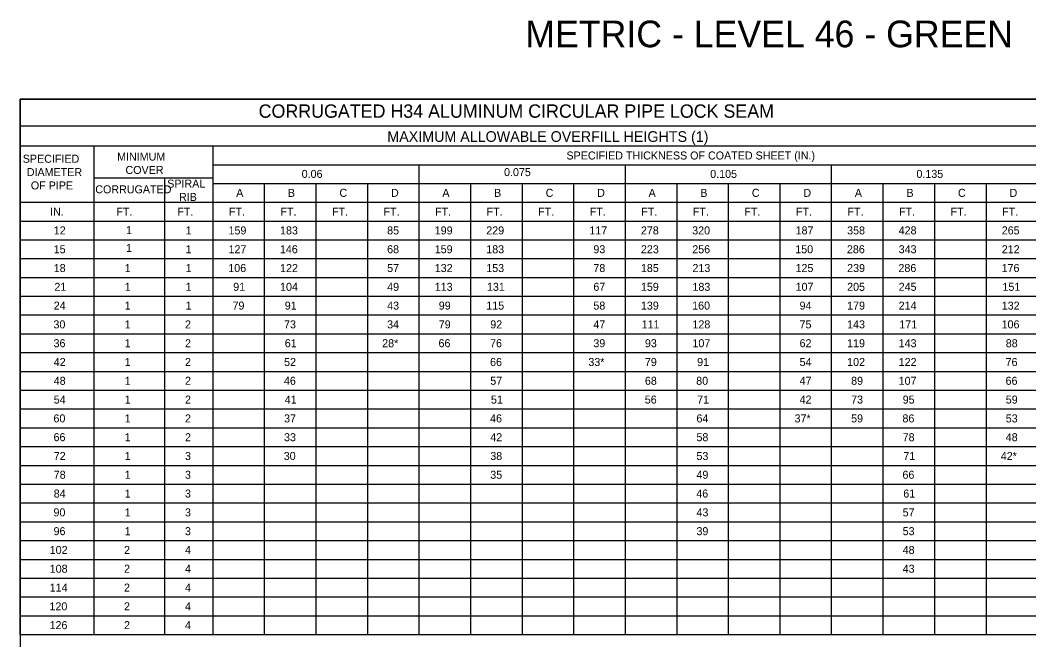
# Model space of a CAD drawing. Extents: x -439.1 to -407.9, y -458.1 to -436.2.
# Drawn here: x -439.11 to -420.2, y -447.81 to -436.2 of the extents above; entities that cross this region are included whole.
import ezdxf

# ---------------------------------------------------------------- set-up
doc = ezdxf.new("R2010")
doc.units = 0
for name, color, linetype in [('Draft_Named_Boundary', 7, 'Continuous'), ('Level 4', 7, 'Continuous'), ('Level 46', 7, 'Continuous')]:
    doc.layers.add(name, color=color, linetype=linetype)

msp = doc.modelspace()

# ---------------------------------------------------------------- linework, layer by layer
at = {"layer": 'Draft_Named_Boundary'}
msp.add_lwpolyline([(-439.109, -458.051), (-407.859, -458.051), (-407.859, -437.676), (-439.109, -437.676)], close=True, dxfattribs=at)
at = {"layer": 'Level 4'}
for p, q in [((-439.109, -437.676), (-416.17, -437.676)), ((-439.109, -447.71), (-439.109, -437.676)), ((-439.109, -438.177), (-416.17, -438.177)), ((-439.109, -438.552), (-416.17, -438.552)), ((-437.72, -447.71), (-437.72, -438.552)), ((-435.493, -447.71), (-435.493, -438.552)), ((-435.493, -438.905), (-416.17, -438.905)), ((-431.629, -447.71), (-431.629, -438.905)), ((-427.764, -447.71), (-427.764, -438.905)), ((-423.9, -447.71), (-423.9, -438.905)), ((-437.72, -439.154), (-435.493, -439.154)), ((-436.396, -447.71), (-436.396, -439.154)), ((-435.493, -439.257), (-416.17, -439.257)), ((-434.527, -447.71), (-434.527, -439.257)), ((-433.561, -447.71), (-433.561, -439.257)), ((-432.595, -447.71), (-432.595, -439.257)), ((-430.663, -447.71), (-430.663, -439.257)), ((-429.696, -447.71), (-429.696, -439.257)), ((-428.73, -447.71), (-428.73, -439.257)), ((-426.798, -447.71), (-426.798, -439.257)), ((-425.832, -447.71), (-425.832, -439.257)), ((-424.866, -447.71), (-424.866, -439.257)), ((-422.933, -447.71), (-422.933, -439.257)), ((-421.967, -447.71), (-421.967, -439.257)), ((-421.001, -447.71), (-421.001, -439.257)), ((-439.109, -439.609), (-416.17, -439.609)), ((-439.109, -439.961), (-416.17, -439.961)), ((-439.109, -440.313), (-416.17, -440.313)), ((-439.109, -440.666), (-416.17, -440.666)), ((-439.109, -441.018), (-416.17, -441.018)), ((-439.109, -441.37), (-416.17, -441.37)), ((-439.109, -441.722), (-416.17, -441.722)), ((-439.109, -442.075), (-416.17, -442.075)), ((-439.109, -442.427), (-416.17, -442.427)), ((-439.109, -442.779), (-416.17, -442.779)), ((-439.109, -443.131), (-416.17, -443.131)), ((-439.109, -443.483), (-416.17, -443.483)), ((-439.109, -443.836), (-416.17, -443.836)), ((-439.109, -444.188), (-416.17, -444.188)), ((-439.109, -444.54), (-416.17, -444.54)), ((-439.109, -444.892), (-416.17, -444.892)), ((-439.109, -445.245), (-416.17, -445.245)), ((-439.109, -445.597), (-416.17, -445.597)), ((-439.109, -445.949), (-416.17, -445.949)), ((-439.109, -446.301), (-416.17, -446.301)), ((-439.109, -446.654), (-416.17, -446.654)), ((-439.109, -447.006), (-416.17, -447.006)), ((-439.109, -447.358), (-416.17, -447.358)), ((-439.109, -447.71), (-416.17, -447.71))]:
    msp.add_line(p, q, dxfattribs=at)

# ---------------------------------------------------------------- texts
for s, height, p in [('CORRUGATED H34 ALUMINUM CIRCULAR PIPE LOCK SEAM', 0.25, (-434.64, -438.026)), ('MAXIMUM ALLOWABLE OVERFILL HEIGHTS (1)', 0.2, (-432.228, -438.478)), ('SPECIFIED', 0.15, (-439.06, -438.869)), ('MINIMUM', 0.15, (-437.292, -438.829)), ('SPECIFIED THICKNESS OF COATED SHEET (IN.)', 0.15, (-428.87, -438.808)), ('COVER', 0.15, (-437.135, -439.079)), ('DIAMETER', 0.15, (-438.985, -439.119)), ('0.06', 0.15, (-433.833, -439.153)), ('0.075', 0.15, (-430.04, -439.119)), ('0.105', 0.15, (-426.176, -439.153)), ('0.135', 0.15, (-422.311, -439.153)), ('OF PIPE', 0.15, (-438.909, -439.369)), ('CORRUGATED', 0.15, (-437.701, -439.442)), ('SPIRAL', 0.15, (-436.353, -439.335)), ('RIB', 0.15, (-436.132, -439.585)), ('A', 0.15, (-435.06, -439.508)), ('B', 0.15, (-434.091, -439.508)), ('C', 0.15, (-433.125, -439.508)), ('D', 0.15, (-432.159, -439.508)), ('A', 0.15, (-431.196, -439.508)), ('B', 0.15, (-430.227, -439.508)), ('C', 0.15, (-429.261, -439.508)), ('D', 0.15, (-428.295, -439.508)), ('A', 0.15, (-427.331, -439.508)), ('B', 0.15, (-426.362, -439.508)), ('C', 0.15, (-425.396, -439.508)), ('D', 0.15, (-424.43, -439.508)), ('A', 0.15, (-423.466, -439.508)), ('B', 0.15, (-422.498, -439.508)), ('C', 0.15, (-421.532, -439.508)), ('D', 0.15, (-420.566, -439.508)), ('IN.', 0.15, (-438.548, -439.86)), ('FT.', 0.15, (-437.306, -439.86)), ('FT.', 0.15, (-436.164, -439.86)), ('FT.', 0.15, (-435.197, -439.86)), ('FT.', 0.15, (-434.231, -439.86)), ('FT.', 0.15, (-433.265, -439.86)), ('FT.', 0.15, (-432.299, -439.86)), ('FT.', 0.15, (-431.333, -439.86)), ('FT.', 0.15, (-430.367, -439.86)), ('FT.', 0.15, (-429.401, -439.86)), ('FT.', 0.15, (-428.434, -439.86)), ('FT.', 0.15, (-427.468, -439.86)), ('FT.', 0.15, (-426.502, -439.86)), ('FT.', 0.15, (-425.536, -439.86)), ('FT.', 0.15, (-424.57, -439.86)), ('FT.', 0.15, (-423.604, -439.86)), ('FT.', 0.15, (-422.638, -439.86)), ('FT.', 0.15, (-421.671, -439.86)), ('FT.', 0.15, (-420.705, -439.86)), ('12', 0.15, (-438.48, -440.212)), ('1', 0.15, (-437.125, -440.205)), ('1', 0.15, (-436.008, -440.212)), ('159', 0.15, (-435.204, -440.212)), ('183', 0.15, (-434.238, -440.212)), ('85', 0.15, (-432.231, -440.212)), ('199', 0.15, (-431.339, -440.212)), ('229', 0.15, (-430.373, -440.212)), ('117', 0.15, (-428.441, -440.212)), ('278', 0.15, (-427.475, -440.212)), ('320', 0.15, (-426.514, -440.212)), ('187', 0.15, (-424.576, -440.212)), ('358', 0.15, (-423.61, -440.212)), ('428', 0.15, (-422.644, -440.212)), ('265', 0.15, (-420.712, -440.212)), ('15', 0.15, (-438.48, -440.565)), ('1', 0.15, (-437.125, -440.541)), ('1', 0.15, (-436.008, -440.565)), ('127', 0.15, (-435.204, -440.565)), ('146', 0.15, (-434.241, -440.565)), ('68', 0.15, (-432.231, -440.565)), ('159', 0.15, (-431.339, -440.565)), ('183', 0.15, (-430.373, -440.565)), ('93', 0.15, (-428.366, -440.565)), ('223', 0.15, (-427.475, -440.565)), ('256', 0.15, (-426.512, -440.565)), ('150', 0.15, (-424.582, -440.565)), ('286', 0.15, (-423.614, -440.565)), ('343', 0.15, (-422.644, -440.565)), ('212', 0.15, (-420.712, -440.565)), ('18', 0.15, (-438.48, -440.917)), ('1', 0.15, (-437.15, -440.917)), ('1', 0.15, (-436.008, -440.917)), ('106', 0.15, (-435.208, -440.917)), ('122', 0.15, (-434.238, -440.917)), ('57', 0.15, (-432.231, -440.917)), ('132', 0.15, (-431.339, -440.917)), ('153', 0.15, (-430.373, -440.917)), ('78', 0.15, (-428.366, -440.917)), ('185', 0.15, (-427.475, -440.917)), ('213', 0.15, (-426.509, -440.917)), ('125', 0.15, (-424.577, -440.917)), ('239', 0.15, (-423.61, -440.917)), ('286', 0.15, (-422.648, -440.917)), ('176', 0.15, (-420.715, -440.917)), ('21', 0.15, (-438.467, -441.269)), ('1', 0.15, (-437.15, -441.269)), ('1', 0.15, (-436.008, -441.269)), ('91', 0.15, (-435.116, -441.269)), ('104', 0.15, (-434.238, -441.269)), ('49', 0.15, (-432.231, -441.269)), ('113', 0.15, (-431.339, -441.269)), ('131', 0.15, (-430.361, -441.269)), ('67', 0.15, (-428.366, -441.269)), ('159', 0.15, (-427.475, -441.269)), ('183', 0.15, (-426.509, -441.269)), ('107', 0.15, (-424.576, -441.269)), ('205', 0.15, (-423.61, -441.269)), ('245', 0.15, (-422.644, -441.269)), ('151', 0.15, (-420.699, -441.269)), ('24', 0.15, (-438.48, -441.621)), ('1', 0.15, (-437.15, -441.621)), ('1', 0.15, (-436.008, -441.621)), ('79', 0.15, (-435.129, -441.621)), ('91', 0.15, (-434.15, -441.621)), ('43', 0.15, (-432.231, -441.621)), ('99', 0.15, (-431.264, -441.621)), ('115', 0.15, (-430.373, -441.621)), ('58', 0.15, (-428.366, -441.621)), ('139', 0.15, (-427.475, -441.621)), ('160', 0.15, (-426.514, -441.621)), ('94', 0.15, (-424.501, -441.621)), ('179', 0.15, (-423.61, -441.621)), ('214', 0.15, (-422.644, -441.621)), ('132', 0.15, (-420.712, -441.621)), ('30', 0.15, (-438.485, -441.973)), ('1', 0.15, (-437.15, -441.973)), ('2', 0.15, (-436.02, -441.973)), ('73', 0.15, (-434.163, -441.973)), ('34', 0.15, (-432.231, -441.973)), ('79', 0.15, (-431.264, -441.973)), ('92', 0.15, (-430.298, -441.973)), ('47', 0.15, (-428.366, -441.973)), ('111', 0.15, (-427.462, -441.973)), ('128', 0.15, (-426.509, -441.973)), ('75', 0.15, (-424.502, -441.973)), ('143', 0.15, (-423.61, -441.973)), ('171', 0.15, (-422.632, -441.973)), ('106', 0.15, (-420.715, -441.973)), ('36', 0.15, (-438.483, -442.326)), ('1', 0.15, (-437.15, -442.326)), ('2', 0.15, (-436.02, -442.326)), ('61', 0.15, (-434.15, -442.326)), ('28*', 0.15, (-432.324, -442.326)), ('66', 0.15, (-431.268, -442.326)), ('76', 0.15, (-430.302, -442.326)), ('39', 0.15, (-428.366, -442.326)), ('93', 0.15, (-427.4, -442.326)), ('107', 0.15, (-426.509, -442.326)), ('62', 0.15, (-424.501, -442.326)), ('119', 0.15, (-423.61, -442.326)), ('143', 0.15, (-422.644, -442.326)), ('88', 0.15, (-420.637, -442.326)), ('42', 0.15, (-438.48, -442.678)), ('1', 0.15, (-437.15, -442.678)), ('2', 0.15, (-436.02, -442.678)), ('52', 0.15, (-434.163, -442.678)), ('66', 0.15, (-430.302, -442.678)), ('33*', 0.15, (-428.46, -442.678)), ('79', 0.15, (-427.4, -442.678)), ('91', 0.15, (-426.421, -442.678)), ('54', 0.15, (-424.501, -442.678)), ('102', 0.15, (-423.61, -442.678)), ('122', 0.15, (-422.644, -442.678)), ('76', 0.15, (-420.64, -442.678)), ('48', 0.15, (-438.48, -443.03)), ('1', 0.15, (-437.15, -443.03)), ('2', 0.15, (-436.02, -443.03)), ('46', 0.15, (-434.166, -443.03)), ('57', 0.15, (-430.298, -443.03)), ('68', 0.15, (-427.4, -443.03)), ('80', 0.15, (-426.439, -443.03)), ('47', 0.15, (-424.501, -443.03)), ('89', 0.15, (-423.535, -443.03)), ('107', 0.15, (-422.644, -443.03)), ('66', 0.15, (-420.64, -443.03)), ('54', 0.15, (-438.48, -443.382)), ('1', 0.15, (-437.15, -443.382)), ('2', 0.15, (-436.02, -443.382)), ('41', 0.15, (-434.15, -443.382)), ('51', 0.15, (-430.286, -443.382)), ('56', 0.15, (-427.403, -443.382)), ('71', 0.15, (-426.421, -443.382)), ('42', 0.15, (-424.501, -443.382)), ('73', 0.15, (-423.535, -443.382)), ('95', 0.15, (-422.569, -443.382)), ('59', 0.15, (-420.637, -443.382)), ('60', 0.15, (-438.485, -443.735)), ('1', 0.15, (-437.15, -443.735)), ('2', 0.15, (-436.02, -443.735)), ('37', 0.15, (-434.163, -443.735)), ('46', 0.15, (-430.302, -443.735)), ('64', 0.15, (-426.434, -443.735)), ('37*', 0.15, (-424.595, -443.735)), ('59', 0.15, (-423.535, -443.735)), ('86', 0.15, (-422.573, -443.735)), ('53', 0.15, (-420.637, -443.735)), ('66', 0.15, (-438.483, -444.087)), ('1', 0.15, (-437.15, -444.087)), ('2', 0.15, (-436.02, -444.087)), ('33', 0.15, (-434.163, -444.087)), ('42', 0.15, (-430.298, -444.087)), ('58', 0.15, (-426.434, -444.087)), ('78', 0.15, (-422.569, -444.087)), ('48', 0.15, (-420.637, -444.087)), ('72', 0.15, (-438.48, -444.439)), ('1', 0.15, (-437.15, -444.439)), ('3', 0.15, (-436.02, -444.439)), ('30', 0.15, (-434.169, -444.439)), ('38', 0.15, (-430.298, -444.439)), ('53', 0.15, (-426.434, -444.439)), ('71', 0.15, (-422.557, -444.439)), ('42*', 0.15, (-420.73, -444.439)), ('78', 0.15, (-438.48, -444.791)), ('1', 0.15, (-437.15, -444.791)), ('3', 0.15, (-436.02, -444.791)), ('35', 0.15, (-430.298, -444.791)), ('49', 0.15, (-426.434, -444.791)), ('66', 0.15, (-422.573, -444.791)), ('84', 0.15, (-438.48, -445.143)), ('1', 0.15, (-437.15, -445.143)), ('3', 0.15, (-436.02, -445.143)), ('46', 0.15, (-426.437, -445.143)), ('61', 0.15, (-422.557, -445.143)), ('90', 0.15, (-438.485, -445.496)), ('1', 0.15, (-437.15, -445.496)), ('3', 0.15, (-436.02, -445.496)), ('43', 0.15, (-426.434, -445.496)), ('57', 0.15, (-422.569, -445.496)), ('96', 0.15, (-438.483, -445.848)), ('1', 0.15, (-437.15, -445.848)), ('3', 0.15, (-436.02, -445.848)), ('39', 0.15, (-426.434, -445.848)), ('53', 0.15, (-422.569, -445.848)), ('102', 0.15, (-438.555, -446.2)), ('2', 0.15, (-437.163, -446.2)), ('4', 0.15, (-436.02, -446.2)), ('48', 0.15, (-422.569, -446.2)), ('108', 0.15, (-438.555, -446.552)), ('2', 0.15, (-437.163, -446.552)), ('4', 0.15, (-436.02, -446.552)), ('43', 0.15, (-422.569, -446.552)), ('114', 0.15, (-438.555, -446.905)), ('2', 0.15, (-437.163, -446.905)), ('4', 0.15, (-436.02, -446.905)), ('120', 0.15, (-438.56, -447.257)), ('2', 0.15, (-437.163, -447.257)), ('4', 0.15, (-436.02, -447.257)), ('126', 0.15, (-438.558, -447.609)), ('2', 0.15, (-437.163, -447.609)), ('4', 0.15, (-436.02, -447.609))]:
    msp.add_text(s, height=height, dxfattribs=at).set_placement(p)
at = {"layer": 'Level 46'}
msp.add_text('METRIC - LEVEL 46 - GREEN', height=0.5, dxfattribs=at).set_placement((-429.642, -436.705))

doc.saveas('drawing.dxf')
